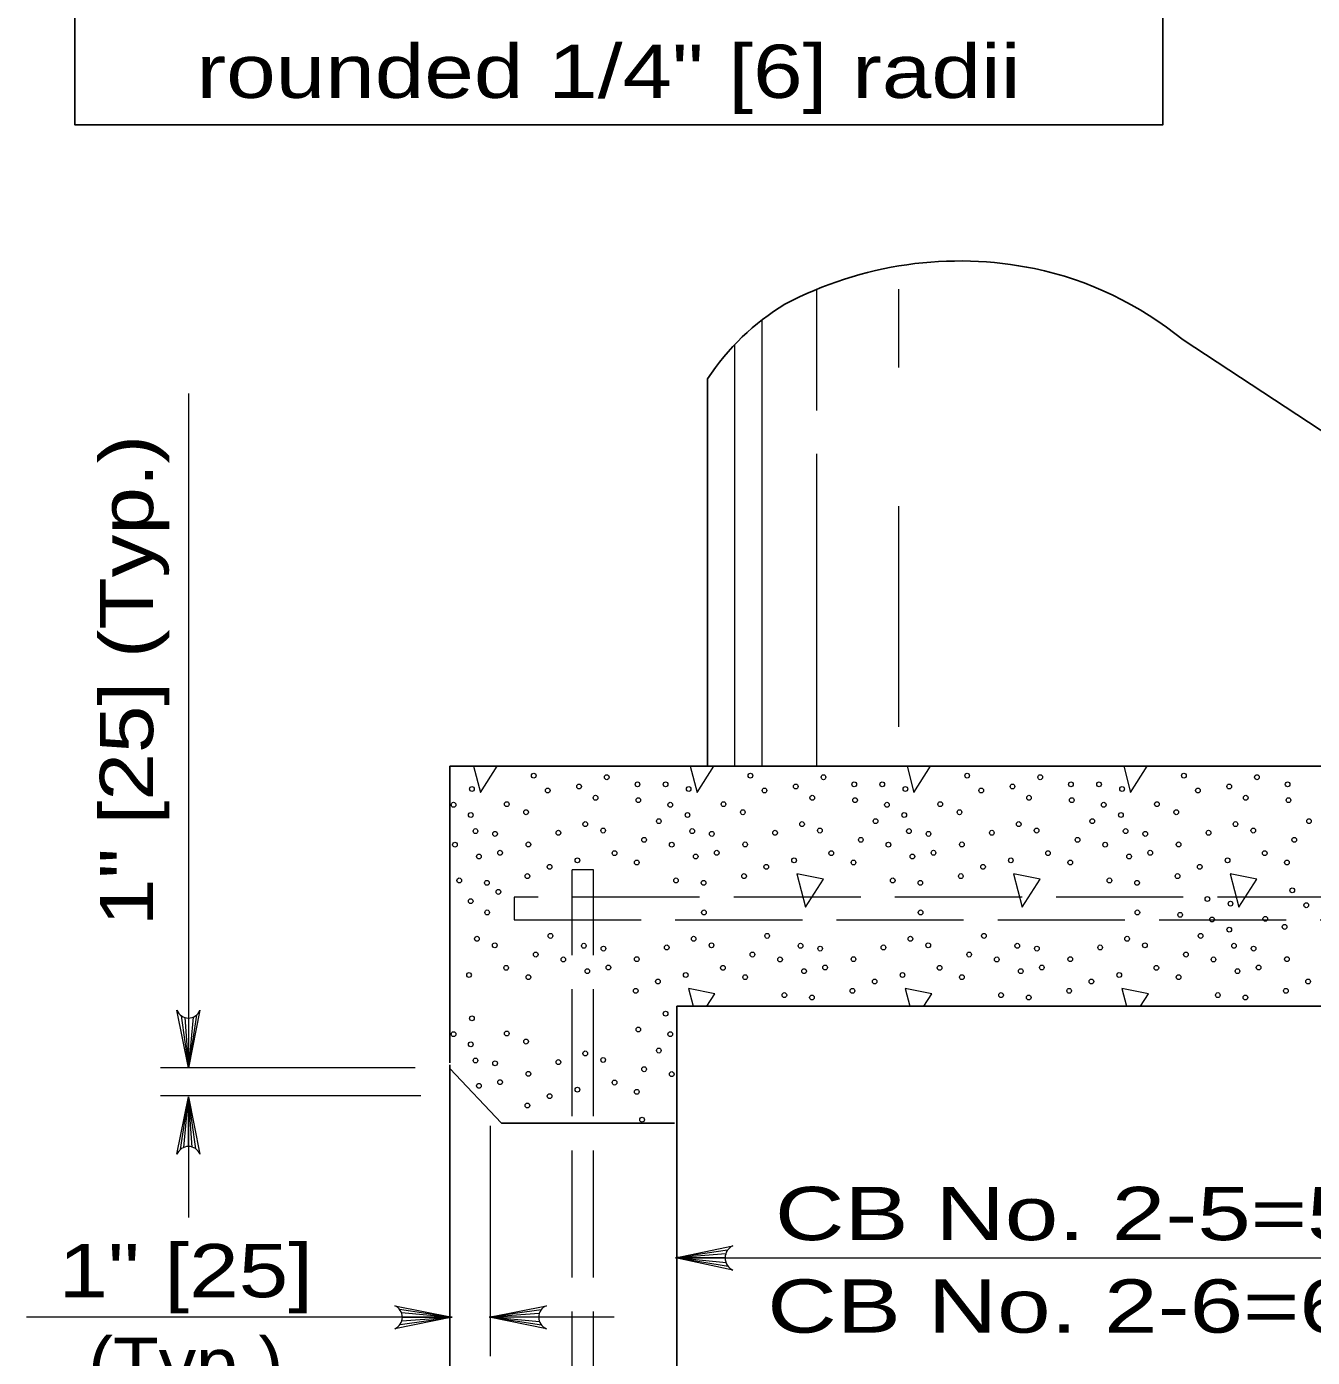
# Model space of a CAD drawing. Extents: x 1329.9 to 1363.9, y 715.5 to 737.5.
# Drawn here: x 1346.592 to 1350.356, y 722.725 to 726.621 of the extents above; entities that cross this region are included whole.
import ezdxf
from ezdxf.enums import TextEntityAlignment as Align

# ---------------------------------------------------------------- set-up
doc = ezdxf.new("R2010")
doc.units = 0
doc.header["$LTSCALE"] = 0.062
doc.linetypes.add('LONG_DASHED', pattern=[7.5, 6, -1.5])
doc.layers.add('1', color=7, linetype='Continuous', lineweight=13)

msp = doc.modelspace()

# ---------------------------------------------------------------- linework, layer by layer
at = {"layer": '1'}
for p, q in [((1348.90525, 725.49717), (1348.90525, 725.85242)), ((1349.14533, 725.62333), (1349.14533, 725.85242)), ((1348.74525, 724.4555), (1348.74525, 725.76342)), ((1348.66525, 724.4555), (1348.66525, 725.69083)), ((1347.06558, 725.5475), (1347.06558, 723.57275)), ((1348.90525, 724.4555), (1348.90525, 725.37067)), ((1349.14533, 724.57117), (1349.14533, 725.21692)), ((1348.52892, 723.80475), (1348.54267, 723.75258)), ((1349.16333, 723.80475), (1349.17708, 723.75258)), ((1349.79767, 723.80475), (1349.81142, 723.75258)), ((1347.04433, 723.72508), (1347.06558, 723.57275)), ((1347.05483, 723.71992), (1347.06558, 723.57275)), ((1347.08917, 723.72683), (1347.06558, 723.57275)), ((1347.07925, 723.721), (1347.06558, 723.57275)), ((1347.06558, 723.71833), (1347.06558, 723.57275)), ((1347.7295, 723.57275), (1346.98383, 723.57275)), ((1347.74583, 723.49092), (1346.98383, 723.49092)), ((1347.04208, 723.3335), (1347.06558, 723.48758)), ((1347.05192, 723.33933), (1347.06558, 723.48758)), ((1347.06558, 723.342), (1347.06558, 723.48758)), ((1347.07633, 723.3405), (1347.06558, 723.48758)), ((1347.08692, 723.33533), (1347.06558, 723.48758)), ((1347.06558, 723.48758), (1347.06558, 723.13383)), ((1347.94858, 723.40242), (1347.94858, 722.72792)), ((1348.64325, 723.0385), (1348.49092, 723.01592)), ((1348.63808, 723.02733), (1348.49092, 723.01592)), ((1348.49092, 723.01592), (1352.86367, 723.01592)), ((1348.6365, 723.01592), (1348.49092, 723.01592)), ((1348.63917, 723.00142), (1348.49092, 723.01592)), ((1348.645, 722.991), (1348.49092, 723.01592)), ((1347.68333, 722.86558), (1347.83742, 722.84208)), ((1347.68917, 722.85575), (1347.83742, 722.84208)), ((1348.09767, 722.86333), (1347.94533, 722.84208)), ((1348.0925, 722.85283), (1347.94533, 722.84208)), ((1347.83742, 722.84208), (1346.59183, 722.84208)), ((1347.68508, 722.82075), (1347.83742, 722.84208)), ((1347.69025, 722.83133), (1347.83742, 722.84208)), ((1347.69183, 722.84208), (1347.83742, 722.84208)), ((1348.31158, 722.84208), (1347.94533, 722.84208)), ((1348.09092, 722.84208), (1347.94533, 722.84208)), ((1348.09358, 722.82842), (1347.94533, 722.84208)), ((1348.09942, 722.8185), (1347.94533, 722.84208))]:
    msp.add_line(p, q, dxfattribs=at)
at = {"layer": '1', "lineweight": 25}
for p, q in [((1351.20408, 724.89942), (1349.977, 725.70392)), ((1348.58517, 724.4555), (1348.58517, 725.59008)), ((1348.49467, 723.41067), (1348.49467, 723.75258)), ((1347.83075, 719.34), (1347.83075, 723.58142)), ((1348.49467, 719.51625), (1348.49467, 723.41067))]:
    msp.add_line(p, q, dxfattribs=at)
at = {"layer": '1', "linetype": 'LONG_DASHED'}
for p, q in [((1348.18833, 718.7105), (1348.18833, 724.15242)), ((1348.25092, 724.15183), (1348.18833, 724.15183)), ((1348.25092, 718.7105), (1348.25092, 724.15242))]:
    msp.add_line(p, q, dxfattribs=at)
at = {"layer": '1', "lineweight": 25}
msp.add_lwpolyline([(1346.73325, 726.90575), (1349.91742, 726.90575), (1349.91742, 726.33358), (1346.73325, 726.33358)], close=True, dxfattribs=at)
for points in [[(1353.483, 723.55867), (1353.483, 724.4555), (1347.83075, 724.4555), (1347.83075, 723.58692)], [(1348.49467, 723.75258), (1352.86742, 723.75258), (1352.86742, 723.41067), (1353.34492, 723.41067), (1353.483, 723.55683)], [(1347.83075, 723.5705), (1347.98183, 723.41067), (1348.48867, 723.41067)]]:
    msp.add_lwpolyline(points, dxfattribs=at)
at = {"layer": '1'}
for points in [[(1347.90017, 724.4555), (1347.92008, 724.37908), (1347.96875, 724.4555)], [(1348.5345, 724.4555), (1348.55458, 724.37908), (1348.60317, 724.4555)], [(1349.16892, 724.4555), (1349.18892, 724.37908), (1349.2375, 724.4555)], [(1349.80325, 724.4555), (1349.82333, 724.37908), (1349.87192, 724.4555)], [(1348.58333, 723.75258), (1348.60675, 723.78958), (1348.52892, 723.80475)], [(1349.21775, 723.75258), (1349.24117, 723.78958), (1349.16333, 723.80475)], [(1349.85217, 723.75258), (1349.87558, 723.78958), (1349.79767, 723.80475)], [(1347.09925, 723.741), (1347.06558, 723.57275), (1347.032, 723.741)], [(1347.032, 723.31942), (1347.06558, 723.48758), (1347.09925, 723.31942)], [(1348.65917, 722.98033), (1348.49092, 723.01592), (1348.65917, 723.05158)], [(1347.66917, 722.87567), (1347.83742, 722.84208), (1347.66917, 722.80842)], [(1348.11358, 722.80842), (1347.94533, 722.84208), (1348.11358, 722.87567)]]:
    msp.add_lwpolyline(points, dxfattribs=at)
for points in [[(1348.84608, 724.14058), (1348.87175, 724.04325), (1348.924, 724.12542)], [(1349.4805, 724.14058), (1349.50617, 724.04325), (1349.55833, 724.12542)], [(1350.11492, 724.14058), (1350.14058, 724.04325), (1350.19283, 724.12542)]]:
    msp.add_lwpolyline(points, close=True, dxfattribs=at)
at = {"layer": '1', "linetype": 'LONG_DASHED'}
msp.add_lwpolyline([(1348.01858, 724.00633), (1353.28167, 724.00633), (1353.28167, 724.07267), (1348.01858, 724.07267)], close=True, dxfattribs=at)
at = {"layer": '1'}
for centre, start, end in [((1347.06557, 723.75457), 202.08782, 337.91395), ((1347.06564, 723.3058), 22.08782, 157.91395), ((1347.65561, 722.84203), 292.08782, 67.91395), ((1348.12714, 722.8421), 112.08782, 247.91395)]:
    msp.add_arc(centre, 0.03631, start, end, dxfattribs=at)
at = {"layer": '1', "lineweight": 25}
for centre, major_axis, start_param, end_param in [((1349.32237, 724.71498), (0, 1.22023), 6.0913628, 6.7427401), ((1349.34034, 724.83137), (0, 1.10247), 5.6254463, 6.0881824), ((1349.15573, 725.16916), (0, 0.73619), 0.5184487, 0.9622613)]:
    msp.add_ellipse(centre, major_axis=major_axis, ratio=0.944544, start_param=start_param, end_param=end_param, dxfattribs=at)
at = {"layer": '1'}
for centre in [(1348.07616, 724.428), (1348.29001, 724.42346), (1348.37993, 724.40259), (1348.46219, 724.40259), (1348.71056, 724.428), (1348.9244, 724.42346), (1349.01433, 724.40259), (1349.09659, 724.40259), (1349.34496, 724.428), (1349.5588, 724.42346), (1349.64873, 724.40259), (1349.73099, 724.40259), (1349.97936, 724.428), (1350.1932, 724.42346), (1350.28313, 724.40259), (1347.89541, 724.38898), (1348.11729, 724.38445), (1348.20891, 724.39626), (1348.25717, 724.36329), (1348.52981, 724.38898), (1348.75169, 724.38445), (1348.84331, 724.39626), (1348.89157, 724.36329), (1349.16421, 724.38898), (1349.38609, 724.38445), (1349.47771, 724.39626), (1349.52597, 724.36329), (1349.79861, 724.38898), (1350.02049, 724.38445), (1350.1121, 724.39626), (1350.16037, 724.36329), (1347.84149, 724.34275), (1347.99734, 724.34454), (1348.05385, 724.32098), (1348.38247, 724.35635), (1348.47588, 724.34275), (1348.63173, 724.34454), (1348.68825, 724.32098), (1349.01687, 724.35635), (1349.11028, 724.34275), (1349.26613, 724.34454), (1349.32265, 724.32098), (1349.65127, 724.35635), (1349.74468, 724.34275), (1349.90053, 724.34454), (1349.95705, 724.32098), (1350.28566, 724.35635), (1347.89197, 724.31281), (1348.2272, 724.28622), (1348.44242, 724.29467), (1348.52637, 724.31281), (1348.8616, 724.28622), (1349.07682, 724.29467), (1349.16077, 724.31281), (1349.496, 724.28622), (1349.71122, 724.29467), (1349.79517, 724.31281), (1350.1304, 724.28622), (1350.34562, 724.29467), (1347.90572, 724.26568), (1347.96308, 724.25745), (1348.14838, 724.26087), (1348.27943, 724.26719), (1348.54012, 724.26568), (1348.59748, 724.25745), (1348.78277, 724.26087), (1348.91383, 724.26719), (1349.17452, 724.26568), (1349.23188, 724.25745), (1349.41717, 724.26087), (1349.54823, 724.26719), (1349.80891, 724.26568), (1349.86627, 724.25745), (1350.05157, 724.26087), (1350.18263, 724.26719), (1347.84571, 724.22577), (1348.06072, 724.22661), (1348.39933, 724.23999), (1348.48011, 724.22577), (1348.69512, 724.22661), (1349.03373, 724.23999), (1349.11451, 724.22577), (1349.32952, 724.22661), (1349.66813, 724.23999), (1349.74891, 724.22577), (1349.96392, 724.22661), (1350.30253, 724.23999), (1347.91592, 724.1913), (1347.97762, 724.20221), (1348.20404, 724.1801), (1348.31279, 724.20098), (1348.37792, 724.17378), (1348.55032, 724.1913), (1348.61202, 724.20221), (1348.83844, 724.1801), (1348.94719, 724.20098), (1349.01232, 724.17378), (1349.18472, 724.1913), (1349.24641, 724.20221), (1349.47284, 724.1801), (1349.58159, 724.20098), (1349.64672, 724.17378), (1349.81912, 724.1913), (1349.88081, 724.20221), (1350.10724, 724.1801), (1350.21599, 724.20098), (1350.28112, 724.17378), (1348.0576, 724.13387), (1348.12263, 724.16107), (1348.692, 724.13387), (1348.75703, 724.16107), (1349.3264, 724.13387), (1349.39143, 724.16107), (1349.9608, 724.13387), (1350.02583, 724.16107), (1347.8583, 724.12122), (1347.93913, 724.11423), (1347.97281, 724.08764), (1348.4927, 724.12122), (1348.57353, 724.11423), (1349.12709, 724.12122), (1349.20793, 724.11423), (1349.76149, 724.12122), (1349.84233, 724.11423), (1350.29656, 724.09217), (1347.89171, 724.06044), (1350.04819, 724.06676), (1350.1158, 724.05316), (1350.33769, 724.04863), (1347.93998, 724.02747), (1348.57437, 724.02747), (1349.20877, 724.02747), (1349.84317, 724.02747), (1349.96847, 724.02053), (1350.21773, 724.00872), (1350.06188, 724.00693), (1350.11237, 723.97699), (1350.27425, 723.98516), (1347.91, 723.9504), (1347.96223, 723.93137), (1348.12522, 723.95885), (1348.5444, 723.9504), (1348.59663, 723.93137), (1348.75962, 723.95885), (1349.1788, 723.9504), (1349.23103, 723.93137), (1349.39402, 723.95885), (1349.8132, 723.9504), (1349.86543, 723.93137), (1350.02842, 723.95885), (1348.08213, 723.90417), (1348.22292, 723.92986), (1348.28028, 723.92163), (1348.46557, 723.92505), (1348.71653, 723.90417), (1348.85732, 723.92986), (1348.91468, 723.92163), (1349.09997, 723.92505), (1349.35093, 723.90417), (1349.49171, 723.92986), (1349.54908, 723.92163), (1349.73437, 723.92505), (1349.98533, 723.90417), (1350.12611, 723.92986), (1350.18347, 723.92163), (1347.99559, 723.86516), (1348.16291, 723.88995), (1348.23312, 723.85547), (1348.29482, 723.86639), (1348.37792, 723.89079), (1348.62999, 723.86516), (1348.79731, 723.88995), (1348.86752, 723.85547), (1348.92921, 723.86639), (1349.01232, 723.89079), (1349.26439, 723.86516), (1349.43171, 723.88995), (1349.50192, 723.85547), (1349.56361, 723.86639), (1349.64672, 723.89079), (1349.89879, 723.86516), (1350.06611, 723.88995), (1350.13632, 723.85547), (1350.19801, 723.86639), (1350.28112, 723.89079), (1347.88684, 723.84428), (1348.06072, 723.83796), (1348.43983, 723.82525), (1348.52124, 723.84428), (1348.69512, 723.83796), (1349.07423, 723.82525), (1349.15564, 723.84428), (1349.32952, 723.83796), (1349.70863, 723.82525), (1349.79004, 723.84428), (1349.96392, 723.83796), (1350.34303, 723.82525), (1348.3748, 723.79805), (1348.80989, 723.7854), (1348.89073, 723.7784), (1349.0092, 723.79805), (1349.44429, 723.7854), (1349.52513, 723.7784), (1349.6436, 723.79805), (1350.07869, 723.7854), (1350.15953, 723.7784), (1350.278, 723.79805), (1347.89541, 723.71734), (1348.46219, 723.73094), (1347.84149, 723.67111), (1347.99734, 723.6729), (1348.38247, 723.68471), (1348.47588, 723.67111), (1347.89197, 723.64116), (1348.05385, 723.64933), (1348.44242, 723.62303), (1347.90572, 723.59404), (1347.96308, 723.58581), (1348.14838, 723.58922), (1348.2272, 723.61458), (1348.27943, 723.59555), (1348.06072, 723.55497), (1348.39933, 723.56835), (1348.48011, 723.55413), (1347.91592, 723.51965), (1347.97762, 723.53057), (1348.20404, 723.50846), (1348.31279, 723.52933), (1348.37792, 723.50213), (1348.12263, 723.48943), (1348.0576, 723.46223), (1348.39336, 723.42053)]:
    msp.add_ellipse(centre, major_axis=(0, 0.00718), ratio=0.944544, dxfattribs=at)
msp.add_ellipse((1348.67278, 723.01595), major_axis=(0, 0.03844), ratio=0.944544, start_param=0.3855052, end_param=2.7561184, dxfattribs=at)

# ---------------------------------------------------------------- texts
for s, width, p in [('rounded 1/4" [6] radii', 1.25, (1348.29512, 726.41267)), ('1" [25]', 1.25, (1347.05762, 722.90058)), ('(Typ.)', 1.05, (1347.05762, 722.6265))]:
    msp.add_text(s, height=0.156, dxfattribs=dict(at, width=width)).set_placement(p, align=Align.CENTER)
at = {"layer": '1', "width": 1.2}
msp.add_text('1" [25] (Typ.)', height=0.156, rotation=90, dxfattribs=at).set_placement((1346.96217, 724.70679), align=Align.CENTER)
at = {"layer": '1', "width": 1.35}
for s, p in [('CB No. 2-5=5\'-0" [1500]', (1348.78225, 723.06783)), ('CB No. 2-6=6\'-0" [1800]', (1348.75983, 722.79692))]:
    msp.add_text(s, height=0.156, dxfattribs=at).set_placement(p)

doc.saveas('drawing.dxf')
